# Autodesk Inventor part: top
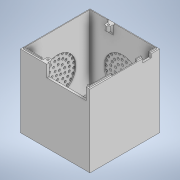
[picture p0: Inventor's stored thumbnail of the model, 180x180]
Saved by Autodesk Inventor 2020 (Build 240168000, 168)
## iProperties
Created: 2019-04
Part Number: top
Material: Generic
Document SubType Name: Modeling
Designer: Eli
Density: 1 g/cm^3
Appearance: Default
Author: Eli
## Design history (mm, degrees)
node "Blocks"
  sketch "respeaker"
    geometry: L1 (1.2, 0)-(66.2, 0); L2 (66.2, 0)-(66.2, -65); L3 (66.2, -65)-(1.2, -65); L4 (1.2, -65)-(1.2, 0); L5 (38.481, -29.585)-(38.481, -54.622); L6 (38.481, -54.622)-(35.323, -54.622); L7 (35.323, -54.622)-(35.323, -29.585); L8 (35.323, -29.585)-(38.481, -29.585); L9 (64.6, -1.33)-(61.6, -1.33); L10 (61.6, -1.33)-(61.6, -5.13); L11 (61.6, -5.13)-(64.6, -5.13); L12 (64.6, -5.13)-(64.6, -1.33); L13 (64.9, -60.1)-(61.1, -60.1); L14 (61.1, -60.1)-(61.1, -63.1); L15 (61.1, -63.1)-(64.9, -63.1); L16 (64.9, -63.1)-(64.9, -60.1); L17 (2.56, -4.65)-(6.36, -4.65); L18 (6.36, -4.65)-(6.36, -1.65); L19 (6.36, -1.65)-(2.56, -1.65); L20 (2.56, -1.65)-(2.56, -4.65); L21 (6.04, -59.65)-(3.04, -59.65); L22 (3.04, -59.65)-(3.04, -63.45); L23 (3.04, -63.45)-(6.04, -63.45); L24 (6.04, -63.45)-(6.04, -59.65); C1 r 1.4 at (58.2, -3.5); C2 r 1.4 at (58.2, -61.5); C3 r 1.4 at (9.2, -61.5); C4 r 1.4 at (9.2, -3.5); 2 further points
    constraints: 40 end point, 10 parallel, 5 horizontal, 5 perpendicular, 4 centre point, 1 coincident, 2 other
    dimensions: "d0" = 65 distance of L2.end L3.end; "d1" = 65 distance of L1.end L2.end; "d2" = 2.8 diameter of C1; "d3" = 2.8 diameter of C2; "d4" = 58 distance of C1.centre C2.centre; "d5" = 3.5 distance from line of L3 C2.centre; "d9" = 8 distance from line of L2 C2.centre; "d11" = 2.8 diameter of C3; "d12" = 49 distance of C2.centre C3.centre; "d13" = 2.8 diameter of C4; "d14" = 3 distance of L11.end L10.end; "d15" = 3.8 distance of L10.end L9.end; "d17" = 1.33 distance between parallel lines of L1 L9; "d18" = 1.6 distance between parallel lines of L2 L12; "d19" = 8 distance from line of L4 C4.centre; "d20" = 3.5 distance from line of L1 C4.centre; "d21" = 8 distance from line of L4 C3.centre; "d22" = 3.5 distance from line of L3 C3.centre (derived); "d23" = 49 distance of C4.centre C1.centre; "d25" = 3.8 distance of L15.end L14.end; "d26" = 3 distance of L14.end L13.end; "d27" = 1.3 distance between parallel lines of L2 L16; "d28" = 1.9 distance between parallel lines of L3 L15; "d29" = 3.8 distance of L19.end L18.end; "d30" = 3 distance of L18.end L17.end; "d31" = 1.36 distance between parallel lines of L4 L20; "d32" = 1.65 distance between parallel lines of L1 L19; "d33" = 3 distance of L23.end L22.end; "d34" = 3.8 distance of L22.end L21.end; "d35" = 1.84 distance between parallel lines of L4 L22; "d36" = 1.55 distance between parallel lines of L3 L23
  sketch "layout_mirror"
    geometry: L1 (216.994, 68.913)-(216.994, 34.913); L2 (216.994, 68.913)-(218.894, 68.913); L3 (218.894, 68.913)-(218.894, 34.913); L4 (218.894, 34.913)-(216.994, 34.913); L5 (218.461, 68.913)-(218.476, 76.813); L6 (218.476, 76.813)-(219.994, 76.813); L7 (219.994, 76.813)-(219.994, 3.413); L8 (219.994, 3.413)-(214.744, 3.413); L9 (214.744, 3.413)-(214.744, 4.925); L10 (214.744, 4.925)-(218.394, 4.913); L11 (218.394, 4.913)-(218.394, 34.913); L12 (218.394, 34.913)-(218.894, 34.913); L13 (218.894, 34.913)-(218.894, 68.913); L14 (218.894, 68.913)-(218.461, 68.913); L15 (216.994, 6.413)-(214.744, 6.413); L16 (216.994, 34.913)-(216.994, 6.413); L17 (218.394, 34.913)-(216.994, 34.913); L18 (218.394, 4.913)-(218.394, 34.913); L19 (214.744, 4.925)-(218.394, 4.913); L20 (214.744, 6.413)-(214.744, 4.925); L21 (219.994, 76.813)-(219.994, 86.813); L22 (219.994, 76.813)-(216.994, 76.813); L23 (216.994, 86.813)-(216.994, 76.813); L24 (216.994, 86.813)-(219.994, 86.813); L25 (218.461, 68.913)-(218.476, 76.813); L26 (216.994, 76.813)-(216.994, 68.913); L27 (218.476, 76.813)-(216.994, 76.813); L28 (218.461, 68.913)-(218.476, 76.813); L29 (216.994, 68.913)-(218.461, 68.913); L30 (160.494, 96.413)-(216.994, 96.413); L31 (160.494, 97.913)-(160.494, 96.413); L32 (218.494, 97.913)-(160.494, 97.913); L33 (218.494, 86.813)-(218.494, 97.913); L34 (216.994, 86.813)-(218.494, 86.813); L35 (216.994, 96.413)-(216.994, 86.813); L36 (158.994, 10.413)-(158.994, 6.413); L37 (158.994, 6.413)-(160.494, 6.413); L38 (160.494, 6.413)-(160.494, 3.413); L39 (160.494, 3.413)-(123.994, 3.413); L40 (123.994, 3.413)-(123.994, 99.413); L41 (123.994, 99.413)-(219.994, 99.413); L42 (219.994, 99.413)-(219.994, 86.813); L43 (219.994, 86.813)-(218.494, 86.813); L44 (218.494, 86.813)-(218.494, 97.913); L45 (218.494, 97.913)-(160.494, 97.913); L46 (160.494, 97.913)-(160.494, 96.413); L47 (160.494, 96.413)-(158.994, 96.413); L48 (158.994, 96.413)-(158.994, 92.413); L49 (156.494, 89.913)-(154.994, 89.913); L50 (152.494, 92.413)-(152.494, 96.413); L51 (152.494, 96.413)-(150.994, 96.413); L52 (150.994, 96.413)-(150.994, 97.913); L53 (150.994, 97.913)-(125.494, 97.913); L54 (125.494, 97.913)-(125.494, 4.913); L55 (125.494, 4.913)-(150.994, 4.913); L56 (150.994, 4.913)-(150.994, 6.413); L57 (150.994, 6.413)-(152.494, 6.413); L58 (152.494, 6.413)-(152.494, 10.413); L59 (154.994, 12.913)-(156.494, 12.913); L60 (150.994, 6.413)-(126.994, 6.413); L61 (150.994, 4.913)-(150.994, 6.413); L62 (125.494, 4.913)-(150.994, 4.913); L63 (125.494, 97.913)-(125.494, 4.913); L64 (150.994, 97.913)-(125.494, 97.913)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; C1 r 1.25 at (155.744, 93.163); C2 r 1.25 at (155.744, 9.663); A1 r 2.5 centre (156.494, 10.413) between (158.994, 10.413) and (156.494, 12.913); A2 r 2.5 centre (156.494, 92.413) between (156.494, 89.913) and (158.994, 92.413); A3 r 2.5 centre (154.994, 92.413) between (152.494, 92.413) and (154.994, 89.913); A4 r 2.5 centre (154.994, 10.413) between (154.994, 12.913) and (152.494, 10.413); 2 further points
    constraints: 142 end point, 8 point on circle, 6 centre point
sketch "respeaker 4mic array layout"
  geometry: 1 further point
  constraints: 1 other
  node "respeaker:1"
sketch "Sketch2"
  geometry: L1 (0, 0)-(96, 0); L2 (96, 0)-(96, -96); L3 (96, -96)-(0, -96); L4 (0, -96)-(0, 0)
  constraints: 8 end point, 2 parallel, 1 horizontal, 1 perpendicular
  dimensions: "d37" = 96 distance of L2.end L3.end; "d38" = 96 distance of L1.end L2.end
extrude "top/lid" new body sketch "Sketch2" distance "d39" = 3; taper "d40" = 0 deg
sketch "Sketch3"
  geometry: L1 (0, 0)-(0, 96) reference; L2 (0, 96)-(-96, 96) reference; L3 (0, 96)-(-96, 96) reference; L4 (-96, 96)-(-96, 0) reference; L5 (-96, 0)-(0, 0) reference; L6 (0, 0)-(0, 96) reference; L7 (-21.3, 77)-(-21.3, 71.5); L8 (-25.7, 77)-(-25.7, 71.5); L9 (-25.7, 71.5)-(-21.3, 71.5); L10 (-72.5, 74.8)-(-67, 74.8); L11 (-72.5, 79.2)-(-67, 79.2); L12 (-67, 79.2)-(-67, 74.8); L13 (-23.5, 21.2)-(-29, 21.2); L14 (-23.5, 16.8)-(-29, 16.8); L15 (-29, 16.8)-(-29, 21.2); L16 (-70.3, 19)-(-70.3, 24.5); L17 (-74.7, 19)-(-74.7, 24.5); L18 (-74.7, 24.5)-(-70.3, 24.5); C1 r 1.4 at (-23.5, 77); C2 r 1.4 at (-23.5, 19); C3 r 1.4 at (-72.5, 19); C4 r 1.4 at (-72.5, 77); A1 r 2.2 centre (-23.5, 77) between (-21.3, 77) and (-25.7, 77); A2 r 2.2 centre (-23.5, 19) between (-23.5, 21.2) and (-23.5, 16.8); A3 r 2.2 centre (-72.5, 19) between (-70.3, 19) and (-74.7, 19); A4 r 2.2 centre (-72.5, 77) between (-72.5, 74.8) and (-72.5, 79.2); A5 r 2.2 centre (-23.5, 77) between (-21.3, 77) and (-25.7, 77); A6 r 2.2 centre (-72.5, 77) between (-72.5, 79.2) and (-72.5, 74.8); A7 r 2.2 centre (-23.5, 19) between (-23.5, 16.8) and (-23.5, 21.2); A8 r 2.2 centre (-72.5, 19) between (-74.7, 19) and (-70.3, 19)
  constraints: 24 end point, 16 point on circle, 12 centre point, 7 tangent, 4 horizontal, 4 perpendicular, 4 vertical, 8 other
  dimensions: "d41" = 15.5 dimension on L1; "d42" = 15.5 dimension on L2 (= d41); "d43" = 0.8 radial gap between concentric circles of C1 A1; "d44" = 0.8 radial gap between concentric circles of C2 A2; "d45" = 0.8 radial gap between concentric circles of C3 A3; "d46" = 0.8 radial gap between concentric circles of C4 A4; "d47" = 5.5 distance of L7.start L7.end; "d48" = 5.5 distance of L10.start L10.end; "d49" = 5.5 distance of L11.start L11.end; "d50" = 5.5 distance of L13.start L13.end; "d51" = 5.5 distance of L16.start L16.end; "d52" = 5.5 distance of L17.start L17.end
extrude "legs for the respeaker" join sketch "Sketch3" distance "d53" = 4; taper "d54" = 0 deg
sketch "Sketch4"
  geometry: A1 r 2.2 centre (-23.5, 19) between (-23.5, 16.8) and (-23.5, 21.2) reference; A2 r 2.2 centre (-23.5, 77) between (-21.3, 77) and (-25.7, 77) reference; A3 r 2.2 centre (-72.5, 77) between (-72.5, 79.2) and (-72.5, 74.8) reference; A4 r 2.2 centre (-72.5, 19) between (-74.7, 19) and (-70.3, 19) reference; 5 further points
  constraints: 4 coincident
hole "holes to connect the respeaker" sketch "Sketch4" at (-72.5, 19), (-72.5, 77), (-23.5, 77), (-23.5, 19) diameter "d55" = 2.4; stored, may be unused: countersink angle "d59" = 90 deg, drill point angle "d61" = 0 deg; dims "d56" = 6, "d57" = 4.5, "d58" = 5, "d60" = 6
sketch "Sketch5"
  geometry: C1 r 1.2 at (-23.5, 19) reference; C2 r 2.15 at (-77.2, 18.8); C3 r 2.15 at (-18.8, 18.8); C4 r 2.15 at (-77.2, 77.2); C5 r 2.15 at (-18.8, 77.2); C6 r 2.15 at (-77.2, 18.8); C7 r 2.15 at (-18.8, 18.8); C8 r 2.15 at (-18.8, 77.2); C9 r 2.15 at (-77.2, 77.2); 5 further points
  constraints: 8 centre point, 4 coincident, 4 concentric
  dimensions: "d63" = 0 dimension on C1.centre; "d64" = 0 dimension on C1.centre; "d125" = 58.46 distance of point (-77.16, 18.95) point (-18.7, 18.9) (derived); "d126" = 58.4 distance of point (-77.24, 77.35) point (-77.16, 18.95) (derived); "d127" = 58.37 distance of point (-18.6, 77.27) point (-18.7, 18.9) (derived); "d128" = 58.64 distance of point (-77.24, 77.35) point (-18.6, 77.27) (derived); "d129" = 4.3 diameter of C2; "d130" = 3.3 dimension on C2.centre; "d131" = 3.3 dimension on C2.centre; "d132" = 4.3 diameter of C3; "d134" = 3.3 dimension on C3.centre; "d135" = 4.3 diameter of C4; "d136" = 3.3 dimension on C4.centre; "d137" = 3.3 dimension on C4.centre; "d138" = 4.3 diameter of C5; "d139" = 3.3 dimension on C5.centre; "d140" = 3.3 dimension on C5.centre
extrude "holes for the microphones" cut sketch "Sketch5" stored distance "d69" = 4; taper "d70" = 0 deg
sketch "Sketch6"
  geometry: L1 (-96, 0)-(0, 0) reference; L2 (0, 0)-(0, 96) reference; L3 (0, 96)-(-96, 96) reference; L4 (-96, 96)-(-96, 0) reference; L5 (-93, 3)-(-3, 3); L6 (-3, 3)-(-3, 93); L7 (-3, 93)-(-93, 93); L8 (-93, 93)-(-93, 3)
  constraints: 8 end point, 3 other
  dimensions: "d72" = 3 distance between parallel lines of L4 L8
extrude "walls" join sketch "Sketch6" distance "d73" = 80.8; taper "d74" = 0 deg
sketch "Sketch10"
  geometry: L1 (-96, 96)-(-96, 0) reference; L2 (-96, 0)-(0, 0) reference; L3 (-3, 93)-(-93, 93) reference; L4 (-93, 93)-(-93, 3) reference; L5 (-93, 3)-(-3, 3) reference; L6 (-3, 3)-(-3, 93) reference; L7 (0, 96)-(0, 0) reference; L8 (0, 0)-(-96, 0) reference; L9 (-96, 0)-(-96, 96) reference; L10 (-96, 96)-(0, 96) reference; 10 further points
  dimensions: "d83" = 0 horizontal extent of L1; "d84" = 0 vertical extent of L2
extrude "Extrusion7" join sketch "Sketch10" distance "d85" = 16.2; taper "d86" = 0 deg
sketch "Sketch11"
  geometry: L1 (0, 96)-(-96, 96) reference; L2 (-96, 96)-(-96, 0) reference; 12 further points
  dimensions: "d87" = 0 vertical extent of L1; "d88" = 0 horizontal extent of L2
extrude "rails to connect the two parts" join sketch "Sketch11" distance "d89" = 2; taper "d90" = 0 deg
fillet "Fillet4" dims "d91" = 8
node "fixed size for the power input 1"
node "Direct Edit2"
fillet "Fillet5" dims "d101" = 6.25
sketch "Sketch12"
  geometry: L1 (-67.5, 7)-(-67.5, 3) reference; L2 (-61, 3)-(-67.5, 3) reference; L3 (-67.5, 93)-(-67.5, 89) reference; L4 (-67.5, 93)-(-61, 93) reference; 3 further points
  dimensions: "d102" = 3.25 distance from line of L1 point (-64.25, 6.25); "d103" = 3.25 distance from line of L2 point (-64.25, 6.25); "d104" = 3.25 distance from line of L3 point (-64.25, 89.75); "d105" = 3.25 distance from line of L4 point (-64.25, 89.75)
hole "Hole2" sketch "Sketch12" at (-64.25, 6.25), (-64.25, 89.75) diameter "d106" = 2.7; stored, may be unused: countersink angle "d110" = 90 deg, drill point angle "d112" = 0 deg; dims "d107" = 6, "d108" = 4.5, "d109" = 5, "d111" = 6
node "changed size of the rails"
sketch "Sketch15"
  geometry: L1 (-1, 97)-(-1, 99) reference; L2 (-1, 99)-(0, 99) reference; L3 (0, 99)-(0, 0) reference; L4 (0, 0)-(90, 0) reference; L5 (90, 0)-(90, 99) reference; L6 (90, 99)-(91, 99) reference; L7 (91, 99)-(91, 97) reference; L8 (91, 97)-(93, 97) reference; L9 (93, 97)-(93, -3) reference; L10 (93, -3)-(-3, -3) reference; L11 (-3, -3)-(-3, 97) reference; L12 (-3, 97)-(-1, 97) reference; L13 (0, 99)-(90, 99) reference; C1 r 25.5 at (45, 42)
  constraints: 1 centre point
  dimensions: "d181" = 51 diameter of C1; "d182" = 48 distance from line of L9 C1.centre; "d185" = 55 distance from line of L12 C1.centre
extrude "Extrusion10" cut sketch "Sketch15" distance "d149" = 1.5; taper "d150" = 0 deg
sketch "Sketch16" dims "d164" = 6, "d166" = 6, "d168" = 6
  geometry: L1 (-88, -100)-(8, -100) reference; L2 (-88, -100)-(-88, 0) reference; L3 (8, -100)-(8, 0) reference; L4 (-88, 0)-(8, 0) reference; C1 r 25.5 at (-40, -55); C2 r 1.5 at (-40, -55); C3 r 1.5 at (-45.832, -56.411); C4 r 1.5 at (-41.694, -60.756); C5 r 1.5 at (-35.862, -59.345); C6 r 1.5 at (-34.168, -53.589); C7 r 1.5 at (-38.306, -49.244); C8 r 1.5 at (-44.138, -50.655); C9 r 1.5 at (-51.409, -51.281); C10 r 1.5 at (-51.74, -57.484); C11 r 1.5 at (-48.925, -63.021); C12 r 1.5 at (-43.719, -66.409); C13 r 1.5 at (-37.516, -66.74); C14 r 1.5 at (-31.979, -63.925); C15 r 1.5 at (-28.591, -58.719); C16 r 1.5 at (-28.26, -52.516); C17 r 1.5 at (-31.075, -46.979); C18 r 1.5 at (-36.281, -43.591); C19 r 1.5 at (-42.484, -43.26); C20 r 1.5 at (-48.021, -46.075); C21 r 1.5 at (-57.879, -52.914); C22 r 1.5 at (-57.648, -58.541); C23 r 1.5 at (-55.69, -63.822); C24 r 1.5 at (-52.196, -68.238); C25 r 1.5 at (-47.508, -71.359); C26 r 1.5 at (-42.086, -72.879); C27 r 1.5 at (-36.459, -72.648); C28 r 1.5 at (-31.178, -70.69); C29 r 1.5 at (-26.762, -67.196); C30 r 1.5 at (-23.641, -62.508); C31 r 1.5 at (-22.121, -57.086); C32 r 1.5 at (-22.352, -51.459); C33 r 1.5 at (-24.31, -46.178); C34 r 1.5 at (-27.804, -41.762); C35 r 1.5 at (-32.492, -38.641); C36 r 1.5 at (-37.914, -37.121); C37 r 1.5 at (-43.541, -37.352); C38 r 1.5 at (-48.822, -39.31); C39 r 1.5 at (-53.238, -42.804); C40 r 1.5 at (-56.359, -47.492); C41 r 1.5 at (-63.686, -51.13); C42 r 1.5 at (-63.881, -57.392); C43 r 1.5 at (-62.448, -63.491); C44 r 1.5 at (-59.485, -69.012); C45 r 1.5 at (-55.195, -73.577); C46 r 1.5 at (-49.869, -76.877); C47 r 1.5 at (-43.87, -78.686); C48 r 1.5 at (-37.608, -78.881); C49 r 1.5 at (-31.509, -77.448); C50 r 1.5 at (-25.988, -74.485); C51 r 1.5 at (-21.423, -70.195); C52 r 1.5 at (-18.123, -64.869); C53 r 1.5 at (-16.314, -58.87); C54 r 1.5 at (-16.119, -52.608); C55 r 1.5 at (-17.552, -46.509); C56 r 1.5 at (-20.515, -40.988); C57 r 1.5 at (-24.805, -36.423); C58 r 1.5 at (-30.131, -33.123); C59 r 1.5 at (-36.13, -31.314); C60 r 1.5 at (-42.392, -31.119); C61 r 1.5 at (-48.491, -32.552); C62 r 1.5 at (-54.012, -35.515); C63 r 1.5 at (-58.577, -39.805); C64 r 1.5 at (-61.877, -45.131); 20 further points
  constraints: 64 centre point, 3 coincident, 235 other
  dimensions: "d171" = 3 diameter of C2; "d170" = 4.5 dimension on C2; "d169" = 3 diameter of C3; "d162" = 360 deg dimension on C2.centre C3.centre (derived); "d167" = 3 diameter of C9; "d159" = 360 deg dimension on C2.centre C9.centre (derived); "d165" = 3 diameter of C21; "d156" = 360 deg dimension on C2.centre C21.centre (derived); "d163" = 3 diameter of C41; "d153" = 360 deg dimension on point (-40, -55) C41.centre (derived); "d176" = 48 distance from line of L2 C1.centre; "d177" = 48 distance from line of L3 point (-40, -55) (derived); "d186" = 55 distance from line of L4 C1.centre
extrude "Extrusion11" cut sketch "Sketch16" taper "d173" = 0 deg; distance "d174" = 1.5
sketch "Sketch17" dims "d200" = 6, "d202" = 6, "d204" = 6
  geometry: L1 (-88, 0)-(8, 0) reference; L2 (-88, -100)-(-88, 0) reference; C1 r 25.5 at (-40, -55); C2 r 1.5 at (-40, -55); C3 r 1.5 at (-43.197, -60.077); C4 r 1.5 at (-37.201, -60.307); C5 r 1.5 at (-34.004, -55.23); C6 r 1.5 at (-36.803, -49.923); C7 r 1.5 at (-42.799, -49.693); C8 r 1.5 at (-45.996, -54.77); C9 r 1.5 at (-51.883, -53.328); C10 r 1.5 at (-51.127, -59.494); C11 r 1.5 at (-47.389, -64.455); C12 r 1.5 at (-41.672, -66.883); C13 r 1.5 at (-35.506, -66.127); C14 r 1.5 at (-30.545, -62.389); C15 r 1.5 at (-28.117, -56.672); C16 r 1.5 at (-28.873, -50.506); C17 r 1.5 at (-32.611, -45.545); C18 r 1.5 at (-38.328, -43.117); C19 r 1.5 at (-44.494, -43.873); C20 r 1.5 at (-49.455, -47.611); C21 r 1.5 at (-57.879, -52.914); C22 r 1.5 at (-57.648, -58.541); C23 r 1.5 at (-55.69, -63.822); C24 r 1.5 at (-52.196, -68.238); C25 r 1.5 at (-47.508, -71.359); C26 r 1.5 at (-42.086, -72.879); C27 r 1.5 at (-36.459, -72.648); C28 r 1.5 at (-31.178, -70.69); C29 r 1.5 at (-26.762, -67.196); C30 r 1.5 at (-23.641, -62.508); C31 r 1.5 at (-22.121, -57.086); C32 r 1.5 at (-22.352, -51.459); C33 r 1.5 at (-24.31, -46.178); C34 r 1.5 at (-27.804, -41.762); C35 r 1.5 at (-32.492, -38.641); C36 r 1.5 at (-37.914, -37.121); C37 r 1.5 at (-43.541, -37.352); C38 r 1.5 at (-48.822, -39.31); C39 r 1.5 at (-53.238, -42.804); C40 r 1.5 at (-56.359, -47.492); C41 r 1.5 at (-63.321, -49.33); C42 r 1.5 at (-63.993, -55.559); C43 r 1.5 at (-63.031, -61.75); C44 r 1.5 at (-60.499, -67.481); C45 r 1.5 at (-56.571, -72.361); C46 r 1.5 at (-51.513, -76.059); C47 r 1.5 at (-45.67, -78.321); C48 r 1.5 at (-39.441, -78.993); C49 r 1.5 at (-33.25, -78.031); C50 r 1.5 at (-27.519, -75.499); C51 r 1.5 at (-22.639, -71.571); C52 r 1.5 at (-18.941, -66.513); C53 r 1.5 at (-16.679, -60.67); C54 r 1.5 at (-16.007, -54.441); C55 r 1.5 at (-16.969, -48.25); C56 r 1.5 at (-19.501, -42.519); C57 r 1.5 at (-23.429, -37.639); C58 r 1.5 at (-28.487, -33.941); C59 r 1.5 at (-34.33, -31.679); C60 r 1.5 at (-40.559, -31.007); C61 r 1.5 at (-46.75, -31.969); C62 r 1.5 at (-52.481, -34.501); C63 r 1.5 at (-57.361, -38.429); C64 r 1.5 at (-61.059, -43.487); 20 further points
  constraints: 64 centre point, 3 coincident, 235 other
  dimensions: "d207" = 3 diameter of C2; "d206" = 4.5 dimension on C2; "d205" = 3 diameter of C3; "d198" = 360 deg dimension on C2.centre C3.centre (derived); "d203" = 3 diameter of C9; "d195" = 360 deg dimension on C2.centre C9.centre (derived); "d201" = 3 diameter of C21; "d192" = 360 deg dimension on C2.centre C21.centre (derived); "d199" = 3 diameter of C41; "d189" = 360 deg dimension on point (-40, -55) C41.centre (derived); "d216" = 55 distance from line of L1 C1.centre; "d217" = 48 distance from line of L2 point (-40, -55)
extrude "Extrusion12" cut sketch "Sketch17" taper "d209" = 0 deg; distance "d210" = 1.5
sketch "Sketch18"
  geometry: L1 (-3, -3)-(-3, 97) reference; L2 (93, 97)-(-3, 97) reference; C1 r 25.5 at (45, 42); 1 further point
  constraints: 1 centre point
  dimensions: "d211" = 51 diameter of C1; "d212" = 48 distance from line of L1 C1.centre; "d213" = 55 distance from line of L2 C1.centre
extrude "Extrusion13" cut sketch "Sketch18" distance "d214" = 1.5; taper "d215" = 0 deg
node "fixed size for power input 2"
body "Solid1"
node "Projected Loop1"
node "respeaker:2" dims "d41" = 15.5, "d42" = 15.5 (= d41), "d43" = 0.8, "d44" = 0.8, "d45" = 0.8, "d46" = 0.8, "d47" = 5.5, "d48" = 5.5, "d49" = 5.5, "d50" = 5.5, "d51" = 5.5, "d52" = 5.5
node "respeaker:3" dims "d63" = 0, "d64" = 0, "d129" = 4.3, "d130" = 3.3, "d131" = 3.3, "d132" = 4.3, "d134" = 3.3, "d135" = 4.3, "d136" = 3.3, "d137" = 3.3, "d138" = 4.3, "d139" = 3.3, "d140" = 3.3
node "layout_mirror:1" dims "d83" = 0, "d84" = 0
node "Project Cut Edges1"
node "layout_mirror:2" dims "d87" = 0, "d88" = 0
move_body "Move1" dims "d94" = 11.2
move_body "Move2" dims "d97" = -10
move_body "Move3" dims "d100" = -10
move_body "Move4" dims "d115" = -0.5
move_body "Move5" dims "d118" = -0.5
move_body "Move6" dims "d121" = -0.5
move_body "Move7" dims "d124" = -0.5
node "Project Cut Edges2"
move_body "Move8" dims "d220" = -0.75
move_body "Move9" dims "d223" = -0.7
other parameters: "d92" = 0, "d93" = 0, "d95" = 0, "d96" = 0, "d98" = 0, "d99" = 0, "d113" = 0, "d114" = 0, "d116" = 0, "d117" = 0, "d119" = 0, "d120" = 0, "d122" = 0, "d123" = 0, "d218" = 0, "d219" = 0, "d221" = 0, "d222" = 0
